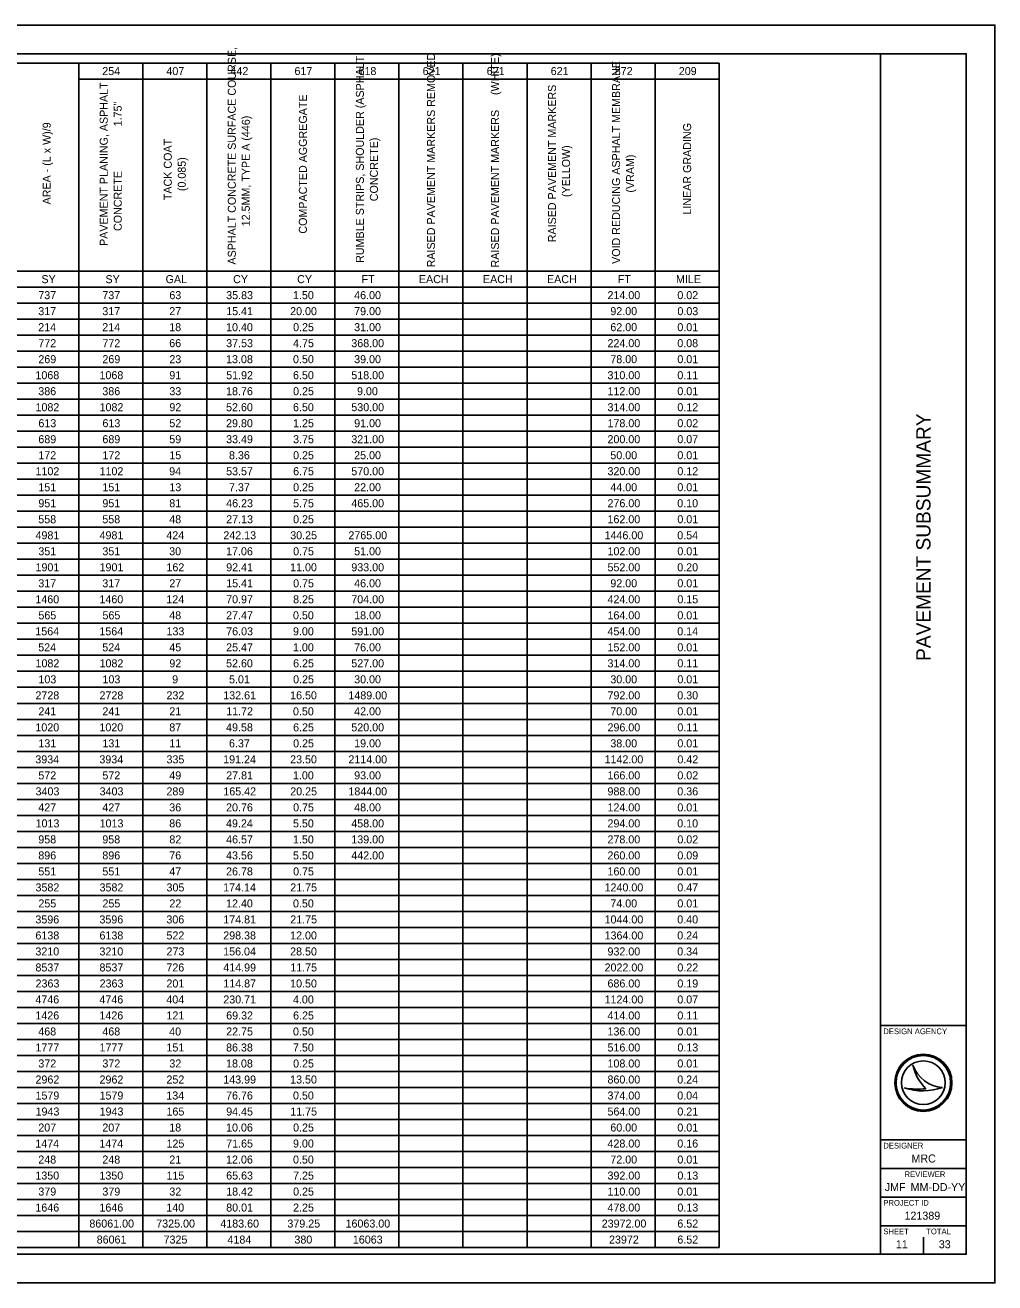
# Model space of a CAD drawing. Extents: x 0 to 34, y 0 to 22.
# Drawn here: x 17.04 to 34, y 0 to 22 of the extents above; entities that cross this region are included whole.
import ezdxf

# ---------------------------------------------------------------- set-up
doc = ezdxf.new("R2010")
doc.units = 0
for name, color, linetype in [('SH_Border', 7, 'Continuous'), ('SH_Cut_Line', 7, 'Continuous'), ('SH_Data', 7, 'Continuous'), ('SH_Text', 7, 'Continuous')]:
    doc.layers.add(name, color=color, linetype=linetype)

msp = doc.modelspace()

# ---------------------------------------------------------------- linework, layer by layer
at = {"layer": 'SH_Border'}
for p, q in [((32, 0.5), (32, 21.5)), ((32, 4.5), (33.5, 4.5)), ((32, 2.5), (33.5, 2.5)), ((32, 2), (33.5, 2)), ((32, 1.5), (33.5, 1.5)), ((32, 1), (33.5, 1))]:
    msp.add_line(p, q, dxfattribs=at)
msp.add_lwpolyline([(1.5, 21.5), (33.5, 21.5), (33.5, 0.5), (1.5, 0.5)], close=True, dxfattribs=at)
at = {"layer": 'SH_Cut_Line'}
msp.add_lwpolyline([(0, 0), (34, 0), (34, 22), (0, 22)], close=True, dxfattribs=at)
at = {"layer": 'SH_Data'}
for p, q in [((4.506, 21.337), (29.179, 21.337)), ((17.979, 21.337), (17.979, 21.057)), ((19.099, 21.337), (19.099, 0.617)), ((20.219, 21.337), (20.219, 0.617)), ((21.339, 21.337), (21.339, 0.617)), ((22.459, 21.337), (22.459, 0.617)), ((23.579, 21.337), (23.579, 0.617)), ((24.699, 21.337), (24.699, 0.617)), ((25.819, 21.337), (25.819, 0.617)), ((26.939, 21.337), (26.939, 0.617)), ((28.059, 21.337), (28.059, 17.697)), ((29.179, 21.337), (29.179, 0.617)), ((17.979, 21.057), (29.179, 21.057)), ((17.979, 21.057), (17.979, 0.617)), ((4.506, 17.697), (29.179, 17.697)), ((28.059, 17.697), (28.059, 17.417)), ((4.506, 17.417), (29.179, 17.417)), ((28.059, 17.417), (28.059, 0.617)), ((4.506, 17.137), (29.179, 17.137)), ((4.506, 16.857), (29.179, 16.857)), ((4.506, 16.577), (29.179, 16.577)), ((4.506, 16.297), (29.179, 16.297)), ((4.506, 16.017), (29.179, 16.017)), ((4.506, 15.737), (29.179, 15.737)), ((4.506, 15.457), (29.179, 15.457)), ((4.506, 15.177), (29.179, 15.177)), ((4.506, 14.897), (29.179, 14.897)), ((4.506, 14.617), (29.179, 14.617)), ((4.506, 14.337), (29.179, 14.337)), ((4.506, 14.057), (29.179, 14.057)), ((4.506, 13.777), (29.179, 13.777)), ((4.506, 13.497), (29.179, 13.497)), ((4.506, 13.217), (29.179, 13.217)), ((4.506, 12.937), (29.179, 12.937)), ((4.506, 12.657), (29.179, 12.657)), ((4.506, 12.377), (29.179, 12.377)), ((4.506, 12.097), (29.179, 12.097)), ((4.506, 11.817), (29.179, 11.817)), ((4.506, 11.537), (29.179, 11.537)), ((4.506, 11.257), (29.179, 11.257)), ((4.506, 10.977), (29.179, 10.977)), ((4.506, 10.697), (29.179, 10.697)), ((4.506, 10.417), (29.179, 10.417)), ((4.506, 10.137), (29.179, 10.137)), ((4.506, 9.857), (29.179, 9.857)), ((4.506, 9.577), (29.179, 9.577)), ((4.506, 9.297), (29.179, 9.297)), ((4.506, 9.017), (29.179, 9.017)), ((4.506, 8.737), (29.179, 8.737)), ((4.506, 8.457), (29.179, 8.457)), ((4.506, 8.177), (29.179, 8.177)), ((4.506, 7.897), (29.179, 7.897)), ((4.506, 7.617), (29.179, 7.617)), ((4.506, 7.337), (29.179, 7.337)), ((4.506, 7.057), (29.179, 7.057)), ((4.506, 6.777), (29.179, 6.777)), ((4.506, 6.497), (29.179, 6.497)), ((4.506, 6.217), (29.179, 6.217)), ((4.506, 5.937), (29.179, 5.937)), ((4.506, 5.657), (29.179, 5.657)), ((4.506, 5.377), (29.179, 5.377)), ((4.506, 5.097), (29.179, 5.097)), ((4.506, 4.817), (29.179, 4.817)), ((4.506, 4.537), (29.179, 4.537)), ((4.506, 4.257), (29.179, 4.257)), ((4.506, 3.977), (29.179, 3.977)), ((32.567, 3.81), (32.567, 3.81)), ((4.506, 3.697), (29.179, 3.697)), ((4.506, 3.417), (29.179, 3.417)), ((32.417, 3.41), (32.417, 3.41)), ((32.75, 3.5), (32.75, 3.5)), ((33.087, 3.419), (33.087, 3.419)), ((4.506, 3.137), (29.179, 3.137)), ((4.506, 2.857), (29.179, 2.857)), ((4.506, 2.577), (29.179, 2.577)), ((4.506, 2.297), (29.179, 2.297)), ((4.506, 2.017), (29.179, 2.017)), ((4.506, 1.737), (29.179, 1.737)), ((4.506, 1.457), (29.179, 1.457)), ((4.506, 1.177), (29.179, 1.177)), ((4.506, 0.897), (29.179, 0.897)), ((32.375, 0.675), (32.375, 0.675)), ((32.75, 0.5), (32.75, 0.8)), ((4.506, 0.617), (29.179, 0.617))]:
    msp.add_line(p, q, dxfattribs=at)
for radius in [0.5, 0.477, 0.477, 0.382]:
    msp.add_circle((32.75, 3.5), radius, dxfattribs=at)
for centre, radius, start, end in [((33.116, 3.998), 0.58, 198.9257, 198.9319), ((33.347, 3.97), 0.796, 191.6379, 191.6421), ((33.116, 3.998), 0.58, 198.9319, 267.1657), ((33.347, 3.97), 0.796, 191.6421, 226.0947), ((32.739, 4.37), 1.013, 251.4576, 290.0832), ((32.648, 4.654), 1.266, 259.4964, 259.4995), ((32.739, 4.37), 1.013, 251.4527, 251.4576), ((32.648, 4.654), 1.266, 259.4995, 276.6672)]:
    msp.add_arc(centre, radius, start, end, dxfattribs=at)

# ---------------------------------------------------------------- texts
msp.add_text('PAVEMENT SUBSUMMARY', height=0.25, rotation=90, dxfattribs=at).set_placement((32.875, 10.879))
for s, height, p in [('DESIGN AGENCY', 0.1, (32.05, 4.35)), ('DESIGNER', 0.1, (32.05, 2.35)), ('MRC', 0.14, (32.541, 2.105)), ('REVIEWER', 0.1, (32.422, 1.85)), ('JMF', 0.14, (32.075, 1.605)), ('MM-DD-YY', 0.14, (32.527, 1.605)), ('PROJECT ID', 0.1, (32.05, 1.35)), ('121389', 0.14, (32.42, 1.105)), ('SHEET', 0.1, (32.05, 0.85)), ('TOTAL', 0.1, (32.8, 0.85)), ('11', 0.14, (32.269, 0.605)), ('33', 0.14, (33.02, 0.605))]:
    msp.add_text(s, height=height, dxfattribs=at).set_placement(p)
at = {"layer": 'SH_Text'}
for s, p in [('ASPHALT CONCRETE SURFACE COURSE, ', (20.726, 17.812)), ('RUMBLE STRIPS, SHOULDER (ASPHALT ', (22.966, 17.842)), ('RAISED PAVEMENT MARKERS REMOVED', (24.209, 17.763)), ('RAISED PAVEMENT MARKERS     (WHITE)', (25.329, 17.761)), ('VOID REDUCING ASPHALT MEMBRANE ', (27.446, 17.824)), ('PAVEMENT PLANING, ASPHALT ', (18.486, 18.138)), ('RAISED PAVEMENT MARKERS     ', (26.326, 18.202)), ('COMPACTED AGGREGATE', (21.969, 18.353)), ('CONCRETE               1.75"', (18.731, 18.399)), ('AREA - (L x W)/9', (17.489, 18.864)), ('12.5MM, TYPE A (446)', (20.971, 18.481)), ('LINEAR GRADING', (28.689, 18.686)), ('CONCRETE)', (23.211, 18.92)), ('TACK COAT                                                           ', (19.606, 18.939)), ('(YELLOW)', (26.571, 18.993)), ('(0.085)', (19.851, 19.097)), ('(VRAM)', (27.691, 19.071))]:
    msp.add_text(s, height=0.14, rotation=90, dxfattribs=at).set_placement(p)
for s, p in [('254', (18.391, 21.127)), ('407', (19.512, 21.127)), ('442', (20.633, 21.127)), ('617', (21.752, 21.127)), ('618', (22.872, 21.127)), ('621', (23.993, 21.127)), ('621', (25.113, 21.127)), ('621', (26.233, 21.127)), ('872', (27.353, 21.127)), ('209', (28.473, 21.127)), ('SY', (17.327, 17.487)), ('SY', (18.447, 17.487)), ('GAL', (19.498, 17.487)), ('CY', (20.679, 17.487)), ('CY', (21.799, 17.487)), ('FT', (22.925, 17.487)), ('EACH', (23.928, 17.487)), ('EACH', (25.048, 17.487)), ('EACH', (26.168, 17.487)), ('FT', (27.405, 17.487)), ('MILE', (28.424, 17.487)), ('737', (17.272, 17.207)), ('737', (18.392, 17.207)), ('63', (19.564, 17.207)), ('35.83', (20.558, 17.207)), ('1.50', (21.726, 17.207)), ('46.00', (22.796, 17.207)), ('214.00', (27.226, 17.207)), ('0.02', (28.448, 17.207)), ('317', (17.272, 16.927)), ('317', (18.392, 16.927)), ('27', (19.563, 16.927)), ('15.41', (20.558, 16.927)), ('20.00', (21.676, 16.927)), ('79.00', (22.796, 16.927)), ('92.00', (27.276, 16.927)), ('0.03', (28.449, 16.927)), ('214', (17.271, 16.647)), ('214', (18.391, 16.647)), ('18', (19.562, 16.647)), ('10.40', (20.556, 16.647)), ('0.25', (21.728, 16.647)), ('31.00', (22.796, 16.647)), ('62.00', (27.276, 16.647)), ('0.01', (28.448, 16.647)), ('772', (17.273, 16.367)), ('772', (18.393, 16.367)), ('66', (19.562, 16.367)), ('37.53', (20.558, 16.367)), ('4.75', (21.728, 16.367)), ('368.00', (22.746, 16.367)), ('224.00', (27.226, 16.367)), ('0.08', (28.447, 16.367)), ('269', (17.273, 16.087)), ('269', (18.393, 16.087)), ('23', (19.564, 16.087)), ('13.08', (20.556, 16.087)), ('0.50', (21.726, 16.087)), ('39.00', (22.796, 16.087)), ('78.00', (27.276, 16.087)), ('0.01', (28.448, 16.087)), ('1068', (17.222, 15.807)), ('1068', (18.342, 15.807)), ('91', (19.563, 15.807)), ('51.92', (20.558, 15.807)), ('6.50', (21.726, 15.807)), ('518.00', (22.746, 15.807)), ('310.00', (27.226, 15.807)), ('0.11', (28.448, 15.807)), ('386', (17.272, 15.527)), ('386', (18.392, 15.527)), ('33', (19.564, 15.527)), ('18.76', (20.556, 15.527)), ('0.25', (21.728, 15.527)), ('9.00', (22.846, 15.527)), ('112.00', (27.226, 15.527)), ('0.01', (28.448, 15.527)), ('1082', (17.223, 15.247)), ('1082', (18.343, 15.247)), ('92', (19.564, 15.247)), ('52.60', (20.556, 15.247)), ('6.50', (21.726, 15.247)), ('530.00', (22.746, 15.247)), ('314.00', (27.226, 15.247)), ('0.12', (28.448, 15.247)), ('613', (17.274, 14.967)), ('613', (18.394, 14.967)), ('52', (19.564, 14.967)), ('29.80', (20.556, 14.967)), ('1.25', (21.728, 14.967)), ('91.00', (22.796, 14.967)), ('178.00', (27.226, 14.967)), ('0.02', (28.448, 14.967)), ('689', (17.273, 14.687)), ('689', (18.393, 14.687)), ('59', (19.563, 14.687)), ('33.49', (20.557, 14.687)), ('3.75', (21.728, 14.687)), ('321.00', (22.746, 14.687)), ('200.00', (27.226, 14.687)), ('0.07', (28.447, 14.687)), ('172', (17.273, 14.407)), ('172', (18.393, 14.407)), ('15', (19.564, 14.407)), ('8.36', (20.607, 14.407)), ('0.25', (21.728, 14.407)), ('25.00', (22.796, 14.407)), ('50.00', (27.276, 14.407)), ('0.01', (28.448, 14.407)), ('1102', (17.223, 14.127)), ('1102', (18.343, 14.127)), ('94', (19.561, 14.127)), ('53.57', (20.557, 14.127)), ('6.75', (21.728, 14.127)), ('570.00', (22.746, 14.127)), ('320.00', (27.226, 14.127)), ('0.12', (28.448, 14.127)), ('151', (17.273, 13.847)), ('151', (18.393, 13.847)), ('13', (19.564, 13.847)), ('7.37', (20.607, 13.847)), ('0.25', (21.728, 13.847)), ('22.00', (22.796, 13.847)), ('44.00', (27.276, 13.847)), ('0.01', (28.448, 13.847)), ('951', (17.273, 13.567)), ('951', (18.393, 13.567)), ('81', (19.563, 13.567)), ('46.23', (20.558, 13.567)), ('5.75', (21.728, 13.567)), ('465.00', (22.746, 13.567)), ('276.00', (27.226, 13.567)), ('0.10', (28.446, 13.567)), ('558', (17.272, 13.287)), ('558', (18.392, 13.287)), ('48', (19.562, 13.287)), ('27.13', (20.558, 13.287)), ('0.25', (21.728, 13.287)), ('162.00', (27.226, 13.287)), ('0.01', (28.448, 13.287)), ('4981', (17.223, 13.007)), ('4981', (18.343, 13.007)), ('424', (19.511, 13.007)), ('242.13', (20.508, 13.007)), ('30.25', (21.678, 13.007)), ('2765.00', (22.695, 13.007)), ('1446.00', (27.175, 13.007)), ('0.54', (28.446, 13.007)), ('351', (17.273, 12.727)), ('351', (18.393, 12.727)), ('30', (19.561, 12.727)), ('17.06', (20.556, 12.727)), ('0.75', (21.728, 12.727)), ('51.00', (22.796, 12.727)), ('102.00', (27.226, 12.727)), ('0.01', (28.448, 12.727)), ('1901', (17.223, 12.447)), ('1901', (18.343, 12.447)), ('162', (19.513, 12.447)), ('92.41', (20.558, 12.447)), ('11.00', (21.676, 12.447)), ('933.00', (22.746, 12.447)), ('552.00', (27.226, 12.447)), ('0.20', (28.446, 12.447)), ('317', (17.272, 12.167)), ('317', (18.392, 12.167)), ('27', (19.563, 12.167)), ('15.41', (20.558, 12.167)), ('0.75', (21.728, 12.167)), ('46.00', (22.796, 12.167)), ('92.00', (27.276, 12.167)), ('0.01', (28.448, 12.167)), ('1460', (17.221, 11.887)), ('1460', (18.341, 11.887)), ('124', (19.511, 11.887)), ('70.97', (20.557, 11.887)), ('8.25', (21.728, 11.887)), ('704.00', (22.746, 11.887)), ('424.00', (27.226, 11.887)), ('0.15', (28.448, 11.887)), ('565', (17.274, 11.607)), ('565', (18.394, 11.607)), ('48', (19.562, 11.607)), ('27.47', (20.557, 11.607)), ('0.50', (21.726, 11.607)), ('18.00', (22.796, 11.607)), ('164.00', (27.226, 11.607)), ('0.01', (28.448, 11.607)), ('1564', (17.22, 11.327)), ('1564', (18.34, 11.327)), ('133', (19.514, 11.327)), ('76.03', (20.558, 11.327)), ('9.00', (21.726, 11.327)), ('591.00', (22.746, 11.327)), ('454.00', (27.226, 11.327)), ('0.14', (28.446, 11.327)), ('524', (17.271, 11.047)), ('524', (18.391, 11.047)), ('45', (19.564, 11.047)), ('25.47', (20.557, 11.047)), ('1.00', (21.726, 11.047)), ('76.00', (22.796, 11.047)), ('152.00', (27.226, 11.047)), ('0.01', (28.448, 11.047)), ('1082', (17.223, 10.767)), ('1082', (18.343, 10.767)), ('92', (19.564, 10.767)), ('52.60', (20.556, 10.767)), ('6.25', (21.728, 10.767)), ('527.00', (22.746, 10.767)), ('314.00', (27.226, 10.767)), ('0.11', (28.448, 10.767)), ('103', (17.274, 10.487)), ('103', (18.394, 10.487)), ('9', (19.613, 10.487)), ('5.01', (20.608, 10.487)), ('0.25', (21.728, 10.487)), ('30.00', (22.796, 10.487)), ('30.00', (27.276, 10.487)), ('0.01', (28.448, 10.487)), ('2728', (17.222, 10.207)), ('2728', (18.342, 10.207)), ('232', (19.513, 10.207)), ('132.61', (20.507, 10.207)), ('16.50', (21.676, 10.207)), ('1489.00', (22.695, 10.207)), ('792.00', (27.226, 10.207)), ('0.30', (28.446, 10.207)), ('241', (17.273, 9.927)), ('241', (18.393, 9.927)), ('21', (19.563, 9.927)), ('11.72', (20.558, 9.927)), ('0.50', (21.726, 9.927)), ('42.00', (22.796, 9.927)), ('70.00', (27.276, 9.927)), ('0.01', (28.448, 9.927)), ('1020', (17.221, 9.647)), ('1020', (18.341, 9.647)), ('87', (19.563, 9.647)), ('49.58', (20.556, 9.647)), ('6.25', (21.728, 9.647)), ('520.00', (22.746, 9.647)), ('296.00', (27.226, 9.647)), ('0.11', (28.448, 9.647)), ('131', (17.273, 9.367)), ('131', (18.393, 9.367)), ('11', (19.563, 9.367)), ('6.37', (20.607, 9.367)), ('0.25', (21.728, 9.367)), ('19.00', (22.796, 9.367)), ('38.00', (27.276, 9.367)), ('0.01', (28.448, 9.367)), ('3934', (17.22, 9.087)), ('3934', (18.34, 9.087)), ('335', (19.514, 9.087)), ('191.24', (20.505, 9.087)), ('23.50', (21.676, 9.087)), ('2114.00', (22.695, 9.087)), ('1142.00', (27.175, 9.087)), ('0.42', (28.448, 9.087)), ('572', (17.273, 8.807)), ('572', (18.393, 8.807)), ('49', (19.563, 8.807)), ('27.81', (20.558, 8.807)), ('1.00', (21.726, 8.807)), ('93.00', (22.796, 8.807)), ('166.00', (27.226, 8.807)), ('0.02', (28.448, 8.807)), ('3403', (17.224, 8.527)), ('3403', (18.344, 8.527)), ('289', (19.513, 8.527)), ('165.42', (20.508, 8.527)), ('20.25', (21.678, 8.527)), ('1844.00', (22.695, 8.527)), ('988.00', (27.226, 8.527)), ('0.36', (28.447, 8.527)), ('427', (17.272, 8.247)), ('427', (18.392, 8.247)), ('36', (19.562, 8.247)), ('20.76', (20.556, 8.247)), ('0.75', (21.728, 8.247)), ('48.00', (22.796, 8.247)), ('124.00', (27.226, 8.247)), ('0.01', (28.448, 8.247)), ('1013', (17.224, 7.967)), ('1013', (18.344, 7.967)), ('86', (19.562, 7.967)), ('49.24', (20.555, 7.967)), ('5.50', (21.726, 7.967)), ('458.00', (22.746, 7.967)), ('294.00', (27.226, 7.967)), ('0.10', (28.446, 7.967)), ('958', (17.272, 7.687)), ('958', (18.392, 7.687)), ('82', (19.564, 7.687)), ('46.57', (20.557, 7.687)), ('1.50', (21.726, 7.687)), ('139.00', (22.746, 7.687)), ('278.00', (27.226, 7.687)), ('0.02', (28.448, 7.687)), ('896', (17.272, 7.407)), ('896', (18.392, 7.407)), ('76', (19.562, 7.407)), ('43.56', (20.556, 7.407)), ('5.50', (21.726, 7.407)), ('442.00', (22.746, 7.407)), ('260.00', (27.226, 7.407)), ('0.09', (28.448, 7.407)), ('551', (17.273, 7.127)), ('551', (18.393, 7.127)), ('47', (19.563, 7.127)), ('26.78', (20.556, 7.127)), ('0.75', (21.728, 7.127)), ('160.00', (27.226, 7.127)), ('0.01', (28.448, 7.127)), ('3582', (17.223, 6.847)), ('3582', (18.343, 6.847)), ('305', (19.514, 6.847)), ('174.14', (20.505, 6.847)), ('21.75', (21.678, 6.847)), ('1240.00', (27.175, 6.847)), ('0.47', (28.447, 6.847)), ('255', (17.274, 6.567)), ('255', (18.394, 6.567)), ('22', (19.564, 6.567)), ('12.40', (20.556, 6.567)), ('0.50', (21.726, 6.567)), ('74.00', (27.276, 6.567)), ('0.01', (28.448, 6.567)), ('3596', (17.221, 6.287)), ('3596', (18.341, 6.287)), ('306', (19.512, 6.287)), ('174.81', (20.507, 6.287)), ('21.75', (21.678, 6.287)), ('1044.00', (27.175, 6.287)), ('0.40', (28.446, 6.287)), ('6138', (17.222, 6.007)), ('6138', (18.342, 6.007)), ('522', (19.513, 6.007)), ('298.38', (20.506, 6.007)), ('12.00', (21.676, 6.007)), ('1364.00', (27.175, 6.007)), ('0.24', (28.446, 6.007)), ('3210', (17.221, 5.727)), ('3210', (18.341, 5.727)), ('273', (19.514, 5.727)), ('156.04', (20.505, 5.727)), ('28.50', (21.676, 5.727)), ('932.00', (27.226, 5.727)), ('0.34', (28.446, 5.727)), ('8537', (17.222, 5.447)), ('8537', (18.342, 5.447)), ('726', (19.512, 5.447)), ('414.99', (20.507, 5.447)), ('11.75', (21.678, 5.447)), ('2022.00', (27.175, 5.447)), ('0.22', (28.448, 5.447)), ('2363', (17.224, 5.167)), ('2363', (18.344, 5.167)), ('201', (19.513, 5.167)), ('114.87', (20.507, 5.167)), ('10.50', (21.676, 5.167)), ('686.00', (27.226, 5.167)), ('0.19', (28.448, 5.167)), ('4746', (17.221, 4.887)), ('4746', (18.341, 4.887)), ('404', (19.511, 4.887)), ('230.71', (20.507, 4.887)), ('4.00', (21.726, 4.887)), ('1124.00', (27.175, 4.887)), ('0.07', (28.447, 4.887)), ('1426', (17.221, 4.607)), ('1426', (18.341, 4.607)), ('121', (19.513, 4.607)), ('69.32', (20.558, 4.607)), ('6.25', (21.728, 4.607)), ('414.00', (27.226, 4.607)), ('0.11', (28.448, 4.607)), ('468', (17.272, 4.327)), ('468', (18.392, 4.327)), ('40', (19.561, 4.327)), ('22.75', (20.558, 4.327)), ('0.50', (21.726, 4.327)), ('136.00', (27.226, 4.327)), ('0.01', (28.448, 4.327)), ('1777', (17.222, 4.047)), ('1777', (18.342, 4.047)), ('151', (19.513, 4.047)), ('86.38', (20.556, 4.047)), ('7.50', (21.726, 4.047)), ('516.00', (27.226, 4.047)), ('0.13', (28.449, 4.047)), ('372', (17.273, 3.767)), ('372', (18.393, 3.767)), ('32', (19.564, 3.767)), ('18.08', (20.556, 3.767)), ('0.25', (21.728, 3.767)), ('108.00', (27.226, 3.767)), ('0.01', (28.448, 3.767)), ('2962', (17.223, 3.487)), ('2962', (18.343, 3.487)), ('252', (19.513, 3.487)), ('143.99', (20.507, 3.487)), ('13.50', (21.676, 3.487)), ('860.00', (27.226, 3.487)), ('0.24', (28.446, 3.487)), ('1579', (17.223, 3.207)), ('1579', (18.343, 3.207)), ('134', (19.511, 3.207)), ('76.76', (20.556, 3.207)), ('0.50', (21.726, 3.207)), ('374.00', (27.226, 3.207)), ('0.04', (28.446, 3.207)), ('1943', (17.224, 2.927)), ('1943', (18.344, 2.927)), ('165', (19.514, 2.927)), ('94.45', (20.558, 2.927)), ('11.75', (21.678, 2.927)), ('564.00', (27.226, 2.927)), ('0.21', (28.448, 2.927)), ('207', (17.272, 2.647)), ('207', (18.392, 2.647)), ('18', (19.562, 2.647)), ('10.06', (20.556, 2.647)), ('0.25', (21.728, 2.647)), ('60.00', (27.276, 2.647)), ('0.01', (28.448, 2.647)), ('1474', (17.22, 2.367)), ('1474', (18.34, 2.367)), ('125', (19.514, 2.367)), ('71.65', (20.558, 2.367)), ('9.00', (21.726, 2.367)), ('428.00', (27.226, 2.367)), ('0.16', (28.447, 2.367)), ('248', (17.272, 2.087)), ('248', (18.392, 2.087)), ('21', (19.563, 2.087)), ('12.06', (20.556, 2.087)), ('0.50', (21.726, 2.087)), ('72.00', (27.276, 2.087)), ('0.01', (28.448, 2.087)), ('1350', (17.221, 1.807)), ('1350', (18.341, 1.807)), ('115', (19.514, 1.807)), ('65.63', (20.558, 1.807)), ('7.25', (21.728, 1.807)), ('392.00', (27.226, 1.807)), ('0.13', (28.449, 1.807)), ('379', (17.273, 1.527)), ('379', (18.393, 1.527)), ('32', (19.564, 1.527)), ('18.42', (20.558, 1.527)), ('0.25', (21.728, 1.527)), ('110.00', (27.226, 1.527)), ('0.01', (28.448, 1.527)), ('1646', (17.221, 1.247)), ('1646', (18.341, 1.247)), ('140', (19.511, 1.247)), ('80.01', (20.558, 1.247)), ('2.25', (21.728, 1.247)), ('478.00', (27.226, 1.247)), ('0.13', (28.449, 1.247)), ('86061.00', (18.165, 0.967)), ('7325.00', (19.335, 0.967)), ('4183.60', (20.455, 0.967)), ('379.25', (21.628, 0.967)), ('16063.00', (22.645, 0.967)), ('23972.00', (27.125, 0.967)), ('6.52', (28.448, 0.967)), ('86061', (18.293, 0.687)), ('7325', (19.463, 0.687)), ('4184', (20.58, 0.687)), ('380', (21.751, 0.687)), ('16063', (22.773, 0.687)), ('23972', (27.253, 0.687)), ('6.52', (28.448, 0.687))]:
    msp.add_text(s, height=0.14, dxfattribs=at).set_placement(p)

doc.saveas('drawing.dxf')
